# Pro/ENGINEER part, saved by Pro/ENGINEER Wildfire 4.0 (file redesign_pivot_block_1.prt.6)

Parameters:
  METRIC = "NO"

Other parameters: PITCH, DRILL_POINT_ANGLE, DRILL_DEPTH, DRILL_DIAMETER, THREAD_DIAMETER, THREADS_PER_INCH, THREAD_DEPTH, THREAD_LENGTH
